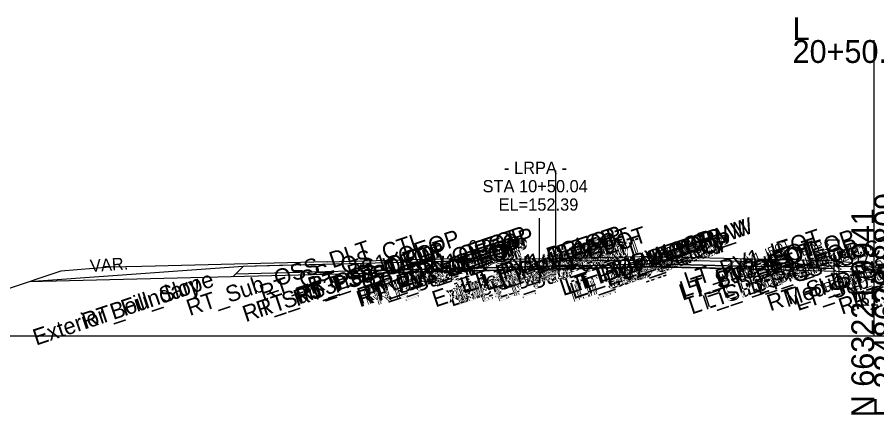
# Model space of a CAD drawing. Extents: x -26 to 2603, y -10 to 9566.
# Drawn here: x 1195.1 to 1300.3, y 490.3 to 539 of the extents above; entities that cross this region are included whole.
import ezdxf

# ---------------------------------------------------------------- set-up
doc = ezdxf.new("R2010")
doc.units = 0
for name, color, linetype in [('Exist Cross Section Cell', 7, 'Continuous'), ('Exist XS Center Line Elevation Label', 7, 'Continuous'), ('Exist XS Ground Line', 7, 'Continuous'), ('Prop CMT Concrete Structures', 7, 'Continuous'), ('Prop CMT Guardrail Graphics', 7, 'Continuous'), ('Prop CMT Pvmt Course 1', 7, 'Continuous'), ('Prop CMT Pvmt Course 2', 7, 'Continuous'), ('Prop CMT Pvmt Course 3 Wedge', 7, 'Continuous'), ('Prop CMT Pvmt Surface', 7, 'Continuous'), ('Prop CMT Pvmt Surface Overlay', 7, 'Continuous'), ('Prop CMT Pvmt Surface Shoulder', 7, 'Continuous'), ('Prop CMT Pvmt Wedge Surface 1', 7, 'Continuous'), ('Prop CMT Pvmt Wedge Surface 2', 7, 'Continuous'), ('Prop CMT Pvmt Wedge Surface 3', 7, 'Continuous'), ('Prop CMT Shld Paved Course 1', 7, 'Continuous'), ('Prop CMT Shld Paved Course 2', 7, 'Continuous'), ('Prop CMT Shld Paved Course 3', 7, 'Continuous'), ('Prop CMT Slope Grass', 7, 'Continuous'), ('Prop CMT Subgrade Earthwork', 7, 'Continuous'), ('Prop XS EOT Tick Mark', 7, 'Continuous'), ('Prop XS SE Text', 7, 'Continuous'), ('Prop XS Side Slope Text', 7, 'Continuous'), ('Prop XS Vertical Lines Alignments', 7, 'Continuous'), ('Scratch_Level_9', 7, 'Continuous'), ('Typical Guardrail CELL', 7, 'Continuous'), ('Typical Median Barrier CELL', 7, 'Continuous')]:
    doc.layers.add(name, color=color, linetype=linetype)

msp = doc.modelspace()

# ---------------------------------------------------------------- linework, layer by layer
at = {"layer": 'Exist Cross Section Cell'}
for p, q in [((1300, 500), (1300, 536.2)), ((1000, 500), (1300, 500)), ((1300, 500), (1600, 500))]:
    msp.add_line(p, q, dxfattribs=at)
at = {"layer": 'Exist XS Ground Line'}
for p, q in [((1253.99, 509.1), (1254.71, 509.11)), ((1254.71, 509.11), (1261.03, 509.15)), ((1261.03, 509.15), (1270.73, 509.25)), ((1270.73, 509.25), (1271.8, 509.26)), ((1271.8, 509.26), (1272.2, 509.26)), ((1272.2, 509.26), (1283.73, 509.12)), ((1283.73, 509.12), (1286.17, 509.05)), ((1286.17, 509.05), (1287.14, 509.03)), ((1287.14, 509.03), (1295.36, 508.53)), ((1295.36, 508.53), (1295.87, 508.5)), ((1295.87, 508.5), (1297.24, 508.47)), ((1297.24, 508.47), (1300, 508.42)), ((1300, 508.42), (1303.89, 508.35))]:
    msp.add_line(p, q, dxfattribs=at)
for points in [[(1245, 509.35), (1251, 509.5)], [(1251, 509.5), (1253, 509.43)], [(1253, 509.43), (1253.99, 509.1)], [(1206.43, 508.39), (1200.43, 507.91)], [(1210.31, 508.48), (1206.43, 508.39)], [(1233, 509.05), (1210.31, 508.48)], [(1233, 509.05), (1245, 509.35)], [(1200.43, 507.91), (1193.61, 505.63)]]:
    msp.add_lwpolyline(points, dxfattribs=at)
at = {"layer": 'Prop CMT Concrete Structures'}
for points in [[(1273, 508.46), (1261, 508.16)], [(1261, 508.15), (1273, 508.45)], [(1273, 508.46), (1285, 508.16)], [(1273, 508.45), (1273, 508.46)], [(1285, 508.15), (1273, 508.45)], [(1246.98, 507.85), (1246.98, 507.85), (1246.98, 507.84), (1246.98, 507.84)], [(1246.98, 507.84), (1246.98, 507.85)], [(1258.99, 508.14), (1248.5, 507.88)], [(1248.5, 507.87), (1258.99, 508.13)], [(1248.5, 507.88), (1248.5, 507.87)], [(1258.99, 508.14), (1263, 508.24)], [(1263, 508.23), (1258.99, 508.13)], [(1258.99, 508.13), (1258.99, 508.14)], [(1258.99, 508.14), (1258.99, 508.14), (1258.99, 508.13), (1258.99, 508.13)], [(1261, 508.16), (1261, 508.15)], [(1263, 508.24), (1263, 508.23)], [(1285, 508.16), (1285, 508.15)]]:
    msp.add_lwpolyline(points, dxfattribs=at)
at = {"layer": 'Prop CMT Guardrail Graphics'}
for points in [[(1295.7, 511.68), (1294.37, 511.68), (1294.1, 511.39)], [(1295.7, 511.68), (1294.37, 511.68), (1294.1, 511.39)], [(1295.7, 505.68), (1295.7, 511.68)], [(1294.1, 511.39), (1294.37, 511.1)], [(1294.1, 511.39), (1294.37, 511.1)], [(1294.37, 511.1), (1294.1, 510.81)], [(1294.37, 511.1), (1294.1, 510.81)], [(1294.1, 510.81), (1294.37, 510.51), (1295.04, 510.51)], [(1294.1, 510.81), (1294.37, 510.51), (1295.04, 510.51)], [(1295.04, 510.51), (1295.04, 505.68)], [(1246.98, 507.85), (1238.28, 507.63), (1237.78, 507.62), (1237.77, 507.61)], [(1237.77, 507.61), (1246.98, 507.84)], [(1246.98, 507.84), (1246.98, 507.85)], [(1285, 508.16), (1285, 508.15)], [(1290.79, 508.01), (1290.78, 508.02), (1290.28, 508.03), (1285, 508.16)], [(1285, 508.15), (1290.79, 508.01)], [(1295.04, 505.68), (1295.7, 505.68)]]:
    msp.add_lwpolyline(points, dxfattribs=at)
at = {"layer": 'Prop CMT Pvmt Course 1'}
msp.add_lwpolyline([(1273, 509.71), (1261, 509.41)], dxfattribs=at)
at = {"layer": 'Prop CMT Pvmt Course 2'}
for p, q in [((1297, 508.95), (1294, 509.19)), ((1297, 508.95), (1300, 507.95)), ((1303, 508.95), (1300, 507.95))]:
    msp.add_line(p, q, dxfattribs=at)
msp.add_lwpolyline([(1222.75, 508.49), (1218.16, 508.13), (1196.53, 506.6)], dxfattribs=at)
msp.add_lwpolyline([(1222.75, 508.49), (1218.16, 508.13), (1196.53, 506.6)], dxfattribs=at)
msp.add_lwpolyline([(1222.75, 508.49), (1218.16, 508.13), (1196.53, 506.6)], dxfattribs=at)
at = {"layer": 'Prop CMT Pvmt Course 3 Wedge'}
for points in [[(1248.5, 507.88), (1246.98, 507.85)], [(1258.99, 508.14), (1258.99, 508.14)]]:
    msp.add_lwpolyline(points, dxfattribs=at)
at = {"layer": 'Prop CMT Pvmt Surface'}
for points in [[(1258.99, 509.39), (1246.98, 509.09)], [(1258.99, 509.39), (1263, 509.49)], [(1273, 509.71), (1261, 509.41)], [(1273, 509.71), (1285, 509.41)]]:
    msp.add_lwpolyline(points, dxfattribs=at)
at = {"layer": 'Prop CMT Pvmt Surface Shoulder'}
for points in [[(1258.99, 509.39), (1246.98, 509.09)], [(1258.99, 509.39), (1263, 509.49)], [(1258.99, 508.48), (1258.99, 509.39)], [(1273, 509.71), (1261, 509.41)], [(1261, 509.41), (1261, 508.49)], [(1263, 509.49), (1263, 508.58)], [(1273, 509.71), (1285, 509.41)], [(1273, 509.59), (1273, 509.71)], [(1273, 508.79), (1273, 509.59), (1273, 509.59)], [(1285, 509.41), (1285, 508.49)], [(1246.98, 509.09), (1248.5, 509.13)], [(1248.5, 509.13), (1248.5, 508.22)], [(1248.5, 508.22), (1258.99, 508.48)], [(1263, 508.58), (1258.99, 508.48)], [(1261, 508.49), (1273, 508.79)], [(1285, 508.49), (1273, 508.79)]]:
    msp.add_lwpolyline(points, dxfattribs=at)
for points in [[(1246.98, 509.09), (1246.98, 508.18), (1246.98, 508.18)], [(1258.99, 508.48), (1258.99, 509.27), (1258.99, 509.27), (1258.99, 508.48)]]:
    msp.add_lwpolyline(points, close=True, dxfattribs=at)
at = {"layer": 'Prop CMT Pvmt Wedge Surface 1'}
for points in [[(1258.99, 509.39), (1258.99, 508.48), (1258.99, 508.48), (1258.99, 509.27), (1258.99, 509.27), (1258.99, 508.48)], [(1263, 508.58), (1263, 509.49)], [(1258.99, 508.48), (1263, 508.58)]]:
    msp.add_lwpolyline(points, dxfattribs=at)
at = {"layer": 'Prop CMT Pvmt Wedge Surface 2'}
for points in [[(1258.99, 509.39), (1258.99, 508.48)], [(1263, 508.58), (1263, 509.49)], [(1258.99, 508.48), (1263, 508.58)]]:
    msp.add_lwpolyline(points, dxfattribs=at)
at = {"layer": 'Prop CMT Pvmt Wedge Surface 3'}
for points in [[(1258.99, 509.39), (1258.99, 508.14)], [(1263, 508.24), (1263, 509.49)], [(1258.99, 508.14), (1263, 508.24)]]:
    msp.add_lwpolyline(points, dxfattribs=at)
at = {"layer": 'Prop CMT Shld Paved Course 1'}
for points in [[(1285, 508.49), (1285, 509.41)], [(1230.17, 508.68), (1222.75, 508.49), (1221.81, 507.55)], [(1246.98, 508.18), (1246.98, 509.09)], [(1289.94, 508.37), (1285, 508.49)], [(1289, 509.31), (1294, 509.19), (1294.94, 508.24)], [(1238.62, 507.97), (1246.98, 508.18)]]:
    msp.add_lwpolyline(points, dxfattribs=at)
at = {"layer": 'Prop CMT Shld Paved Course 2'}
for points in [[(1285, 508.16), (1285, 508.49)], [(1289, 508.39), (1294.94, 508.24), (1295.28, 507.9)], [(1246.98, 508.18), (1221.81, 507.55), (1221.47, 507.21)], [(1238.28, 507.63), (1246.98, 507.85)], [(1246.98, 507.85), (1246.98, 508.18)], [(1290.28, 508.03), (1285, 508.16)]]:
    msp.add_lwpolyline(points, dxfattribs=at)
at = {"layer": 'Prop CMT Shld Paved Course 3'}
msp.add_line((1246.98, 507.85), (1248.5, 507.87), dxfattribs=at)
msp.add_line((1246.98, 507.85), (1248.5, 507.87), dxfattribs=at)
for points in [[(1273, 508.45), (1261, 508.15)], [(1273, 508.45), (1261, 508.15)], [(1273, 508.45), (1261, 508.15)], [(1273, 508.45), (1285, 508.15)], [(1273, 508.45), (1285, 508.15)], [(1273, 508.45), (1285, 508.15)], [(1237.77, 507.61), (1196.53, 506.6)], [(1237.77, 507.61), (1196.53, 506.6)], [(1246.98, 507.84), (1237.77, 507.61)], [(1246.98, 507.84), (1237.77, 507.61)], [(1246.98, 507.84), (1246.98, 507.84)], [(1246.98, 507.84), (1246.98, 507.84)], [(1258.99, 508.13), (1248.5, 507.87)], [(1258.99, 508.13), (1248.5, 507.87)], [(1258.99, 508.13), (1263, 508.23)], [(1258.99, 508.13), (1263, 508.23)], [(1258.99, 508.13), (1258.99, 508.13)], [(1258.99, 508.13), (1258.99, 508.13)], [(1285, 508.15), (1290.79, 508.01)], [(1285, 508.15), (1290.79, 508.01)], [(1285, 508.15), (1290.79, 508.01)], [(1290.79, 508.01), (1300, 507.78)], [(1309.21, 508.01), (1300, 507.78)]]:
    msp.add_lwpolyline(points, dxfattribs=at)
at = {"layer": 'Prop CMT Slope Grass'}
for points in [[(1258.99, 508.48), (1248.5, 508.22)], [(1258.99, 508.48), (1263, 508.58)], [(1258.99, 508.14), (1258.99, 508.48)], [(1258.99, 508.48), (1258.99, 508.48)], [(1273, 508.79), (1261, 508.49)], [(1261, 508.49), (1261, 508.16)], [(1261, 508.16), (1273, 508.46)], [(1263, 508.58), (1263, 508.24)], [(1273, 508.46), (1273, 508.79)], [(1273, 508.79), (1285, 508.49)], [(1285, 508.16), (1273, 508.46)], [(1285, 508.49), (1285, 508.16)], [(1246.98, 507.85), (1246.98, 507.85), (1246.98, 508.18), (1246.98, 508.18)], [(1246.98, 508.18), (1246.98, 507.85)], [(1248.5, 508.22), (1248.5, 507.88)], [(1248.5, 507.88), (1258.99, 508.14)], [(1263, 508.24), (1258.99, 508.14)]]:
    msp.add_lwpolyline(points, dxfattribs=at)
msp.add_lwpolyline([(1258.99, 508.48), (1258.99, 508.14), (1258.99, 508.14)], close=True, dxfattribs=at)
at = {"layer": 'Prop CMT Subgrade Earthwork'}
for points in [[(1285, 509.41), (1289, 509.31)], [(1246.98, 509.09), (1222.75, 508.49)], [(1289, 509.31), (1294, 509.19)]]:
    msp.add_lwpolyline(points, dxfattribs=at)
at = {"layer": 'Prop XS EOT Tick Mark'}
msp.add_line((1261, 508.49), (1261, 520.21), dxfattribs=at)
at = {"layer": 'Prop XS Vertical Lines Alignments'}
msp.add_line((1258.99, 514.39), (1258.99, 506.39), dxfattribs=at)
at = {"layer": 'Typical Guardrail CELL'}
for points in [[(1258.99, 508.48), (1258.99, 508.48)], [(1248.5, 508.22), (1246.98, 508.18)]]:
    msp.add_lwpolyline(points, dxfattribs=at)
at = {"layer": 'Typical Median Barrier CELL'}
for points in [[(1248.5, 509.13), (1246.98, 509.09)], [(1258.99, 509.27), (1258.99, 509.27)]]:
    msp.add_lwpolyline(points, dxfattribs=at)

# ---------------------------------------------------------------- texts
at = {"layer": 'Exist Cross Section Cell'}
for s, p in [('L', (1290, 536.2)), ('20+50.00 / 1', (1290, 533.4))]:
    msp.add_text(s, height=2.8, dxfattribs=at).set_placement(p)
for s, p in [('E 2248638.8809', (1302.8, 490)), ('N 663221.9941', (1300, 490))]:
    msp.add_text(s, height=2.8, rotation=90, dxfattribs=at).set_placement(p)
at = {"layer": 'Exist XS Center Line Elevation Label'}
msp.add_text('151.42', height=1.5, dxfattribs=at).set_placement((1297.2, 503.67))
at = {"layer": 'Prop CMT Pvmt Surface Overlay'}
msp.add_text('EL=152.39', height=1.5, dxfattribs=at).set_placement((1254.01, 515.31))
at = {"layer": 'Prop XS SE Text'}
for rotation, p in [(1.4199, (1250.36, 510.18)), (1.4321, (1263.23, 510.09)), (358.5679, (1276.23, 510.17))]:
    msp.add_text('0.025', height=1.5, rotation=rotation, dxfattribs=at).set_placement(p)
at = {"layer": 'Prop XS Side Slope Text'}
for s, rotation, p in [('3:1', 341.5651, (1296.7, 509.62)), ('VAR.', 4.0291, (1204.04, 507.79))]:
    msp.add_text(s, height=1.5, rotation=rotation, dxfattribs=at).set_placement(p)
at = {"layer": 'Prop XS Vertical Lines Alignments'}
for s, p in [('- LRPA -', (1254.68, 519.81)), ('STA 10+50.04', (1252.05, 517.56))]:
    msp.add_text(s, height=1.5, dxfattribs=at).set_placement(p)
at = {"layer": 'Scratch_Level_9'}
for s, height, rotation, p in [('LT_PV1_OEEOP_W', 2, 18.4332, (1261.92, 504.84)), ('LT_PV1_IEEOP_W', 2, 18.4332, (1262.53, 505.04)), ('LT_PV1_CP_W', 2, 18.4332, (1264.58, 505.72)), ('RT_PS1_OEOP', 2, 18.4332, (1231.11, 505.04)), ('RT_PV1_OEEOP', 2, 18.4332, (1237.65, 504.93)), ('RT_PV1_OEOT', 2, 18.4332, (1238.47, 505.2)), ('RT_PV1_IEEOP', 2, 18.4332, (1239.78, 505.17)), ('LT_PV1_OEEOP', 2, 18.4332, (1249.7, 505.12)), ('LT_PV1_IEEOP', 2, 18.4332, (1250.31, 505.32)), ('LT_PV1_OEOT', 2, 18.4332, (1252.53, 505.53)), ('LT_PV1_OEOT', 2, 18.4332, (1254.53, 505.62)), ('LT_PV2_OEEOP', 2, 18.4332, (1263.17, 504.46)), ('LT_PV1_CP', 2, 18.4332, (1266.37, 506.45)), ('LT_PV1_OEEOP_W', 1, 22.5575, (1268.16, 507.03)), ('LT_PV1_IEEOP_W', 1, 22.5575, (1268.51, 507.18)), ('LT_PV1_IEOT', 2, 18.4332, (1277.14, 505.74)), ('LT_PS1_IEOP', 2, 18.4332, (1281.2, 505.66)), ('LT_GS_IS_CTL', 2, 18.4332, (1285.84, 504.96)), ('RT_GS_IS_CTL', 2, 18.4332, (1295.8, 504.95)), ('RT_Sub_OSS_DLT', 2, 18.4332, (1216.19, 502.41)), ('RT_GS_OS_CTL', 2, 18.4332, (1225.16, 504.22)), ('RT_PS2_OEOP', 2, 18.4332, (1229.63, 503.92)), ('RT_Sub_OEEOP', 2, 18.4332, (1237.02, 503.46)), ('RT_PV2_OEEOP', 2, 18.4332, (1237.11, 503.83)), ('RT_PV3_OEEOP', 2, 18.4332, (1237.11, 503.5)), ('RT_Sub_OEOT', 2, 18.4332, (1237.84, 503.73)), ('RT_PV2_OEOT', 2, 18.4332, (1237.93, 504.11)), ('RT_PV3_OEOT', 2, 18.4332, (1237.93, 503.77)), ('RT_Sub_IEEOP', 2, 18.4332, (1239.15, 503.7)), ('RT_PV2_IEEOP', 2, 18.4332, (1239.24, 504.08)), ('RT_PV3_IEEOP', 2, 18.4332, (1239.24, 503.74)), ('Exterior Boundary', 2, 18.4332, (1246.27, 503.45)), ('Exterior Boundary', 2, 18.4332, (1248.27, 503.53)), ('LT_Sub_OEEOP', 2, 18.4332, (1249.07, 503.77)), ('LT_PV2_OEEOP', 2, 18.4332, (1249.16, 504.15)), ('LT_PV3_OEEOP', 2, 18.4332, (1249.16, 503.81)), ('LT_Sub_IEEOP', 2, 18.4332, (1249.69, 503.98)), ('LT_PV2_IEEOP', 2, 18.4332, (1249.78, 504.35)), ('LT_PV3_IEEOP', 2, 18.4332, (1249.78, 504.02)), ('LT_Sub_OEOT', 2, 18.4332, (1251.9, 504.07)), ('LT_PV2_OEOT', 2, 18.4332, (1251.99, 504.44)), ('LT_PV3_OEOT', 2, 18.4332, (1251.99, 504.11)), ('LT_Sub_OEOT', 2, 18.4332, (1253.9, 504.15)), ('LT_PV2_OEOT', 2, 18.4332, (1253.99, 504.52)), ('LT_PV3_OEOT', 2, 18.4332, (1253.99, 504.19)), ('PV1_PGL', 2, 18.4332, (1254.06, 506.7)), ('Exterior Boundary', 1, 22.5575, (1256.26, 506.9)), ('LT_PV1_OEOT', 1, 22.5575, (1257.37, 507.36)), ('LT_Sub_OEEOP', 2, 18.4332, (1263.08, 504.09)), ('LT_PV3_OEEOP', 2, 18.4332, (1263.17, 504.13)), ('LT_Sub_IEEOP', 2, 18.4332, (1263.69, 504.3)), ('LT_PV2_IEEOP', 2, 18.4332, (1263.78, 504.67)), ('LT_PV3_IEEOP', 2, 18.4332, (1263.78, 504.34)), ('LT_PV1_CP_W', 1, 22.5575, (1269.42, 507.56)), ('LT_PV1_CP', 1, 22.5575, (1270.3, 508.05)), ('LT_Sub_IEOT', 2, 18.4332, (1276.52, 504.27)), ('LT_PV2_IEOT', 2, 18.4332, (1276.61, 504.64)), ('LT_PV3_IEOT', 2, 18.4332, (1276.61, 504.31)), ('LT_PS2_IEOP', 2, 18.4332, (1281.61, 504.54)), ('LT_PV1_IEOT', 1, 22.5575, (1281.72, 507.51)), ('LT_PS3_IEOP', 2, 18.4332, (1281.94, 504.2)), ('LT_PS1_IEOP', 1, 22.5575, (1285.76, 507.42)), ('RT_Sub_ISS_DLT', 2, 18.4332, (1287.27, 502.99)), ('LT_Sub_ISS_DLT', 2, 18.4332, (1290.64, 503.01)), ('RT_Sub_Trench_Out', 2, 18.4332, (1223.06, 501.65)), ('RT_PS3_Shelf_Out', 2, 18.4332, (1224.76, 502.22)), ('RT_PS3_OEOP', 2, 18.4332, (1229.29, 503.58)), ('Sub_PGL', 2, 18.4332, (1253.44, 505.23)), ('PV2_PGL', 2, 18.4332, (1253.53, 505.6)), ('PV3_PGL', 2, 18.4332, (1253.53, 505.27)), ('LT_PV2_OEOT', 1, 22.5575, (1257.26, 506.4)), ('LT_PV3_OEOT', 1, 22.5575, (1257.26, 506.07)), ('LT_Sub_OEOT', 1, 22.5575, (1257.28, 506.07)), ('LT_PV2_OEEOP', 1, 22.5575, (1268.94, 506.56)), ('LT_PV3_OEEOP', 1, 22.5575, (1268.94, 506.23)), ('LT_Sub_OEEOP', 1, 22.5575, (1268.96, 506.23)), ('LT_PV2_IEEOP', 1, 22.5575, (1269.29, 506.71)), ('LT_PV3_IEEOP', 1, 22.5575, (1269.29, 506.38)), ('LT_Sub_IEEOP', 1, 22.5575, (1269.31, 506.38)), ('LT_Sub_Trench_In', 2, 18.4332, (1277.66, 502.58)), ('LT_PS3_Shelf_In', 2, 18.4332, (1279.34, 503.15)), ('LT_PV2_IEOT', 1, 22.5575, (1281.61, 506.55)), ('LT_PV3_IEOT', 1, 22.5575, (1281.61, 506.22)), ('LT_Sub_Trench_In', 1, 22.5575, (1286.11, 505.52)), ('LT_PS2_IEOP', 1, 22.5575, (1286.59, 506.44)), ('Med_Ditch_CTL', 2, 18.4332, (1289.34, 503.46)), ('LT_GS_IS_CTL', 1, 22.5575, (1291.35, 507.01)), ('RT_Sub_ISS_DLT', 1, 22.5575, (1294.06, 505.42)), ('RT_Sub_Trench_In', 2, 18.4332, (1296.04, 502.56)), ('LT_Sub_ISS_DLT', 1, 22.5575, (1297.45, 505.44)), ('RT_PS3_Shelf_In', 2, 18.4332, (1297.73, 503.14)), ('LT_Sub_IEOT', 1, 22.5575, (1281.64, 506.21)), ('LT_PS3_Shelf_In', 1, 22.5575, (1286.6, 505.74)), ('LT_PS3_IEOP', 1, 22.5575, (1286.93, 506.1)), ('Med_Ditch_CTL', 1, 22.5575, (1295.94, 505.84)), ('RT_Fill_Slope', 2, 18.4332, (1203.39, 500.78)), ('Exterior Boundary', 2, 18.4332, (1197.39, 498.77))]:
    msp.add_text(s, height=height, rotation=rotation, dxfattribs=at).set_placement(p)

doc.saveas('drawing.dxf')
